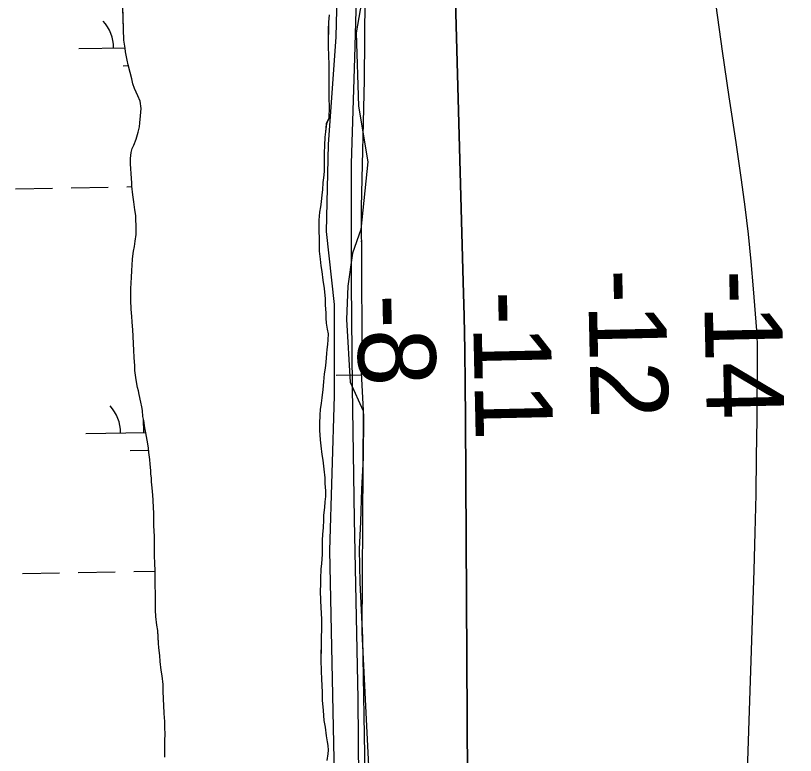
# Model space of a CAD drawing. Extents: x 3925854 to 3964121, y 224593 to 250589.
# Drawn here: x 3942477 to 3943151, y 240491 to 241130 of the extents above; entities that cross this region are included whole.
import ezdxf

# ---------------------------------------------------------------- set-up
doc = ezdxf.new("R2010")
doc.units = 0
for name, color, linetype in [('V-RIVR-EDGE', 7, 'Continuous'), ('V-RIVR-JETY', 7, 'Continuous'), ('V-RIVR-RANG', 7, 'Continuous'), ('V-TOPO-DPTH', 7, 'Continuous'), ('V-TOPO-MINR', 7, 'Continuous'), ('V-TOPO-SHOR', 7, 'Continuous'), ('V-WETL-SWMP', 7, 'Continuous')]:
    doc.layers.add(name, color=color, linetype=linetype)

msp = doc.modelspace()

# ---------------------------------------------------------------- linework, layer by layer
at = {"layer": 'V-RIVR-EDGE'}
msp.add_lwpolyline([(3942781.233, 241173.826), (3942770.996, 241115.474), (3942773.043, 241052.004), (3942781.233, 241003.889), (3942775.091, 240945.538), (3942767.925, 240925.063), (3942763.83, 240896.399), (3942762.806, 240867.736), (3942765.877, 240813.479), (3942777.138, 240788.91), (3942776.115, 240597.475), (3942781.233, 240493.057), (3942784.304, 240431.634), (3942779.186, 240308.789), (3942774.067, 240215.631), (3942769.972, 240146.018), (3942766.901, 240096.88), (3942778.162, 240084.595), (3942767.925, 240046.718), (3942764.854, 240017.03), (3942759.735, 239975.058), (3942740.285, 239935.133), (3942733.119, 239893.161), (3942732.095, 239848.118)], dxfattribs=at)
at = {"layer": 'V-RIVR-JETY'}
for points in [[(3942501.881, 238496.007), (3942530.957, 238578.48), (3942555.82, 238617.728), (3942596.956, 238684.087), (3942673.397, 238798.99), (3942694.77, 238864.612), (3942700.089, 238923.816), (3942705.303, 239063.915), (3942714.359, 239211.498), (3942718.996, 239386.408), (3942726.512, 239566.929), (3942728.732, 239690.128), (3942735.923, 239929.912), (3942744.955, 240165.915), (3942749.64, 240345.527), (3942752.055, 240487.535), (3942748.285, 240668.175), (3942752.491, 240801.701), (3942752.37, 240880.714), (3942745.499, 240943.807), (3942747.22, 241019.038), (3942753.828, 241112.093), (3942757.154, 241251.271)], [(3942538.571, 238553.806), (3942560.622, 238594.024), (3942630.365, 238697.71), (3942697.234, 238796.723), (3942709.735, 238822.929), (3942715.631, 238847.327), (3942722.113, 238928.151), (3942724.245, 239042.886), (3942729.685, 239204.617), (3942737.78, 239350.33), (3942741.958, 239481.033), (3942746.566, 239653.121), (3942749.476, 239843.095), (3942757.257, 240049.011), (3942767.313, 240202.23), (3942774.055, 240398.75), (3942772.697, 240539.858), (3942769.602, 240695.094), (3942767.962, 240808.926), (3942767.018, 240899.237), (3942767.151, 241002.704), (3942769.979, 241093.915), (3942774.399, 241248.132)]]:
    msp.add_lwpolyline(points, dxfattribs=at)
at = {"layer": 'V-TOPO-DPTH'}
msp.add_lwpolyline([(3942983.62, 238887.801), (3942658.91, 239021.11), (3942869.48, 240055.28), (3942865.529, 240782.275), (3942865.271, 240811.75), (3942864.883, 240841.222), (3942864.3, 240870.691), (3942863.587, 240900.157), (3942843.55, 241628.53), (3943150.608, 241695.11)], dxfattribs=at)
at = {"layer": 'V-TOPO-MINR'}
for points in [[(3942843.55, 241628.53), (3942863.587, 240900.157), (3942864.3, 240870.691), (3942864.883, 240841.222), (3942865.271, 240811.75), (3942865.529, 240782.275), (3942869.48, 240055.28), (3942658.91, 239021.11)], [(3943081.741, 241139.181), (3943087.446, 241099.636), (3943093.21, 241060.099), (3943099.014, 241020.569), (3943103.746, 240988.499), (3943106.958, 240964.979), (3943109.832, 240941.421), (3943112.199, 240917.807), (3943114.227, 240894.156), (3943116.91, 240858.352), (3943117.27, 240852.572), (3943117.535, 240846.788), (3943117.655, 240841), (3943117.679, 240835.208), (3943117.233, 240781.568), (3943116.842, 240748.956), (3943116.292, 240716.348), (3943115.504, 240683.745), (3943114.557, 240651.144), (3943096.096, 240086.809)]]:
    msp.add_lwpolyline(points, dxfattribs=at)
at = {"layer": 'V-TOPO-SHOR'}
for points in [[(3942583.969, 241034.288), (3942584.342, 241037.821), (3942584.742, 241043.877), (3942585.313, 241050.1), (3942584.369, 241056.509), (3942582.392, 241060.908), (3942579.599, 241067.504), (3942578.294, 241071.557), (3942577.16, 241075.78), (3942575.87, 241081.181), (3942574.086, 241087.935), (3942573.287, 241091.984), (3942571.845, 241099.07), (3942571.538, 241102.105), (3942570.903, 241105.648), (3942570.434, 241109.187), (3942569.156, 241148.433)], [(3942747.664, 241131.193), (3942747.093, 241124.799), (3942747.025, 241118.401), (3942746.962, 241112.173), (3942746.863, 241102.744), (3942747.136, 241096.512), (3942747.543, 241087.247), (3942747.609, 241077.142), (3942747.535, 241070.24), (3942747.588, 241059.126), (3942747.846, 241051.546), (3942747.408, 241041.786), (3942745.337, 241036.924), (3942744.76, 241029.858), (3942744.039, 241025.32), (3942743.629, 241018.252), (3942743.394, 241011.686), (3942743.519, 241007.645), (3942743.488, 241004.614), (3942743.601, 240999.224), (3942743.396, 240995.691), (3942742.833, 240990.139), (3942742.454, 240986.102), (3942741.883, 240979.711), (3942741.334, 240975.506), (3942740.766, 240969.45), (3942740.215, 240965.08), (3942739.325, 240960.373), (3942738.917, 240953.644), (3942738.862, 240948.255), (3942738.974, 240942.865), (3942739.103, 240939.16), (3942739.193, 240931.583), (3942739.144, 240926.868), (3942739.914, 240919.788), (3942740.699, 240914.224), (3942741.321, 240909.333), (3942742.419, 240901.577), (3942743.525, 240894.493), (3942744.275, 240885.73), (3942744.389, 240880.51), (3942744.817, 240873.096), (3942744.942, 240868.885), (3942745.235, 240864.672), (3942746.189, 240859.276), (3942746.988, 240855.225), (3942746.599, 240850.179), (3942746.222, 240846.14), (3942745.841, 240841.936), (3942745.467, 240838.235), (3942744.885, 240830.831), (3942744.326, 240825.617), (3942743.601, 240820.743), (3942743.023, 240813.845), (3942742.452, 240807.283), (3942741.366, 240800.054), (3942740.811, 240795.346), (3942739.912, 240789.8), (3942739.697, 240785.255), (3942739.447, 240777.512), (3942739.56, 240772.123), (3942740.148, 240763.698), (3942740.596, 240758.473), (3942741.53, 240751.056), (3942742.321, 240745.995), (3942743.083, 240738.409), (3942744.014, 240730.823), (3942744.133, 240725.939), (3942744.574, 240719.705), (3942744.522, 240714.822), (3942744.137, 240710.112), (3942743.75, 240705.234), (3942743.009, 240698.674), (3942742.964, 240694.295), (3942742.56, 240688.069), (3942742.161, 240682.013), (3942741.774, 240677.133), (3942741.864, 240669.555), (3942741.645, 240664.675), (3942741.059, 240656.936), (3942740.502, 240651.889)], [(3942605.83, 240495.752), (3942605.918, 240504.337), (3942606.133, 240508.714), (3942605.867, 240515.62), (3942605.746, 240520.166), (3942605.312, 240527.074), (3942604.884, 240534.488), (3942604.597, 240539.374), (3942604.341, 240547.122), (3942604.224, 240552.174), (3942603.46, 240559.59), (3942602.672, 240564.651), (3942601.906, 240572.069), (3942601.455, 240577.293), (3942600.681, 240583.867), (3942600.388, 240588.08), (3942600.097, 240592.461), (3942599.659, 240599.033), (3942599.032, 240603.415), (3942598.101, 240611.003), (3942597.818, 240616.393), (3942597.738, 240624.815), (3942597.625, 240630.203), (3942597.544, 240638.454), (3942597.453, 240646.032), (3942597.501, 240650.579), (3942597.232, 240657.149), (3942596.794, 240663.551), (3942596.855, 240669.613), (3942596.745, 240675.169), (3942596.802, 240680.725), (3942596.673, 240684.43), (3942596.395, 240689.99), (3942596.268, 240694.033), (3942596.167, 240700.601), (3942595.876, 240704.982), (3942595.606, 240711.552), (3942595.315, 240715.932), (3942594.875, 240722.166), (3942594.424, 240727.391), (3942594.291, 240730.76), (3942593.818, 240733.965), (3942593.685, 240737.334), (3942593.235, 240742.558), (3942592.772, 240746.603), (3942591.993, 240752.673), (3942591.701, 240756.886), (3942590.589, 240763.464), (3942589.309, 240769.877), (3942588.512, 240774.094), (3942587.566, 240780.334), (3942586.929, 240783.877), (3942586.476, 240788.931), (3942586.005, 240792.304), (3942585.206, 240796.353), (3942583.588, 240802.77), (3942582.947, 240805.975), (3942582.306, 240809.014), (3942581.348, 240813.907), (3942580.711, 240817.618), (3942579.933, 240823.686), (3942579.808, 240827.897), (3942579.374, 240834.637), (3942579.107, 240841.542), (3942578.821, 240846.429), (3942578.391, 240853.675), (3942578.106, 240858.559), (3942577.676, 240865.805), (3942577.383, 240870.186), (3942576.609, 240876.592), (3942576.353, 240884.339), (3942576.41, 240889.896), (3942576.451, 240893.936), (3942576.849, 240899.658), (3942576.892, 240903.867), (3942577.295, 240910.261), (3942577.506, 240914.3), (3942577.901, 240920.022), (3942578.815, 240926.915), (3942579.527, 240930.78), (3942580.25, 240935.486), (3942580.983, 240941.204), (3942581.061, 240948.782), (3942580.781, 240954.172), (3942580.648, 240957.541), (3942580.025, 240962.43), (3942579.087, 240969.512), (3942578.141, 240975.584), (3942577.377, 240983), (3942577.24, 240986.033), (3942576.937, 240989.404), (3942576.652, 240994.288), (3942576.349, 240997.659), (3942576.23, 241002.544), (3942576.107, 241006.922), (3942576.834, 241011.967), (3942577.713, 241015.493), (3942579.091, 241018.51), (3942580.998, 241023.71), (3942582.743, 241029.586), (3942583.969, 241034.288)], [(3942740.502, 240651.889), (3942740.25, 240643.81), (3942740.365, 240638.59), (3942740.14, 240633.203), (3942740.224, 240624.952), (3942740.664, 240618.718), (3942741.233, 240608.777), (3942741.162, 240601.873), (3942740.883, 240591.269), (3942740.809, 240584.199), (3942740.701, 240573.59), (3942740.934, 240563.653), (3942741.201, 240556.915), (3942741.758, 240545.629), (3942741.852, 240538.555), (3942742.603, 240529.794), (3942743.187, 240521.198), (3942744.307, 240515.464), (3942745.237, 240507.876), (3942746.196, 240502.815), (3942746.667, 240499.442), (3942746.962, 240495.398), (3942746.593, 240492.371), (3942745.69, 240486.487)], [(3942605.764, 240489.522), (3942605.83, 240495.752)]]:
    msp.add_lwpolyline(points, dxfattribs=at)
at = {"layer": 'V-WETL-SWMP'}
for p, q in [((3942778.222, 241074.964), (3942779.36, 241184.692)), ((3942570.434, 241109.188), (3942569.157, 241148.434)), ((3942747.663, 241131.193), (3942747.092, 241124.8)), ((3942747.092, 241124.8), (3942746.863, 241102.745)), ((3942570.903, 241105.648), (3942570.434, 241109.188)), ((3942531.516, 241101.842), (3942571.456, 241102.568)), ((3942571.539, 241102.105), (3942570.903, 241105.648)), ((3942571.845, 241099.071), (3942571.539, 241102.105)), ((3942573.287, 241091.984), (3942571.845, 241099.071)), ((3942746.863, 241102.745), (3942747.135, 241096.512)), ((3942747.135, 241096.512), (3942747.544, 241087.247)), ((3942569.791, 241087.104), (3942574.284, 241087.186)), ((3942574.086, 241087.935), (3942573.287, 241091.984)), ((3942575.869, 241081.181), (3942574.086, 241087.935)), ((3942747.544, 241087.247), (3942747.608, 241077.143)), ((3942577.16, 241075.78), (3942575.869, 241081.181)), ((3942578.294, 241071.558), (3942577.16, 241075.78)), ((3942747.608, 241077.143), (3942747.536, 241070.24)), ((3942775.667, 240964.847), (3942778.222, 241074.964)), ((3942579.599, 241067.504), (3942578.294, 241071.558)), ((3942582.393, 241060.908), (3942579.599, 241067.504)), ((3942747.536, 241070.24), (3942747.589, 241059.127)), ((3942584.368, 241056.509), (3942582.393, 241060.908)), ((3942747.589, 241059.127), (3942747.847, 241051.547)), ((3942585.312, 241050.101), (3942584.368, 241056.509)), ((3942584.742, 241043.877), (3942585.312, 241050.101)), ((3942747.847, 241051.547), (3942747.409, 241041.786)), ((3942584.343, 241037.82), (3942584.742, 241043.877)), ((3942747.409, 241041.786), (3942745.338, 241036.924)), ((3942582.742, 241029.586), (3942583.969, 241034.287)), ((3942583.969, 241034.287), (3942584.343, 241037.82)), ((3942745.338, 241036.924), (3942744.76, 241029.858)), ((3942580.997, 241023.71), (3942582.742, 241029.586)), ((3942744.039, 241025.319), (3942743.629, 241018.252)), ((3942744.76, 241029.858), (3942744.039, 241025.319)), ((3942577.713, 241015.494), (3942579.091, 241018.51)), ((3942579.091, 241018.51), (3942580.997, 241023.71)), ((3942743.629, 241018.252), (3942743.393, 241011.687)), ((3942576.108, 241006.923), (3942576.834, 241011.967)), ((3942576.834, 241011.967), (3942577.713, 241015.494)), ((3942743.393, 241011.687), (3942743.519, 241007.645)), ((3942576.231, 241002.544), (3942576.108, 241006.923)), ((3942743.519, 241007.645), (3942743.488, 241004.614)), ((3942576.349, 240997.66), (3942576.231, 241002.544)), ((3942743.6, 240999.225), (3942743.395, 240995.691)), ((3942743.488, 241004.614), (3942743.6, 240999.225)), ((3942576.651, 240994.289), (3942576.349, 240997.66)), ((3942576.937, 240989.403), (3942576.651, 240994.289)), ((3942743.395, 240995.691), (3942742.832, 240990.14)), ((3942577.239, 240986.032), (3942576.937, 240989.403)), ((3942577.376, 240983), (3942577.239, 240986.032)), ((3942742.454, 240986.103), (3942741.882, 240979.711)), ((3942742.832, 240990.14), (3942742.454, 240986.103)), ((3942476.865, 240980.757), (3942508.859, 240981.339)), ((3942524.857, 240981.63), (3942556.851, 240982.212)), ((3942572.849, 240982.503), (3942577.419, 240982.586)), ((3942578.141, 240975.583), (3942577.376, 240983)), ((3942741.882, 240979.711), (3942741.333, 240975.507)), ((3942579.088, 240969.512), (3942578.141, 240975.583)), ((3942741.333, 240975.507), (3942740.766, 240969.451)), ((3942580.025, 240962.43), (3942579.088, 240969.512)), ((3942740.215, 240965.079), (3942739.324, 240960.374)), ((3942740.766, 240969.451), (3942740.215, 240965.079)), ((3942776.323, 240853.082), (3942775.667, 240964.847)), ((3942580.648, 240957.541), (3942580.025, 240962.43)), ((3942580.781, 240954.172), (3942580.648, 240957.541)), ((3942739.324, 240960.374), (3942738.918, 240953.643)), ((3942581.062, 240948.781), (3942580.781, 240954.172)), ((3942738.918, 240953.643), (3942738.862, 240948.255)), ((3942580.983, 240941.204), (3942581.062, 240948.781)), ((3942738.862, 240948.255), (3942738.974, 240942.866)), ((3942580.25, 240935.487), (3942580.983, 240941.204)), ((3942738.974, 240942.866), (3942739.104, 240939.16)), ((3942739.104, 240939.16), (3942739.194, 240931.582)), ((3942578.814, 240926.915), (3942579.528, 240930.78)), ((3942579.528, 240930.78), (3942580.25, 240935.487)), ((3942739.194, 240931.582), (3942739.145, 240926.868)), ((3942775.054, 240935.429), (3942775.84, 240935.443)), ((3942577.901, 240920.021), (3942578.814, 240926.915)), ((3942739.145, 240926.868), (3942739.914, 240919.788)), ((3942577.505, 240914.3), (3942577.901, 240920.021)), ((3942739.914, 240919.788), (3942740.698, 240914.223)), ((3942577.295, 240910.261), (3942577.505, 240914.3)), ((3942740.698, 240914.223), (3942741.321, 240909.334)), ((3942576.848, 240899.658), (3942576.892, 240903.867)), ((3942576.892, 240903.867), (3942577.295, 240910.261)), ((3942741.321, 240909.334), (3942742.419, 240901.577)), ((3942576.452, 240893.937), (3942576.848, 240899.658)), ((3942742.419, 240901.577), (3942743.524, 240894.494)), ((3942576.352, 240884.34), (3942576.452, 240893.937)), ((3942743.524, 240894.494), (3942744.275, 240885.73)), ((3942576.609, 240876.592), (3942576.352, 240884.34)), ((3942744.275, 240885.73), (3942744.389, 240880.509)), ((3942744.389, 240880.509), (3942744.817, 240873.096)), ((3942577.384, 240870.186), (3942576.609, 240876.592)), ((3942577.675, 240865.805), (3942577.384, 240870.186)), ((3942744.817, 240873.096), (3942744.942, 240868.885)), ((3942578.105, 240858.56), (3942577.675, 240865.805)), ((3942744.942, 240868.885), (3942745.235, 240864.673)), ((3942745.235, 240864.673), (3942746.189, 240859.275)), ((3942578.391, 240853.674), (3942578.105, 240858.56)), ((3942746.189, 240859.275), (3942746.989, 240855.225)), ((3942578.821, 240846.429), (3942578.391, 240853.674)), ((3942746.6, 240850.178), (3942746.222, 240846.141)), ((3942746.989, 240855.225), (3942746.6, 240850.178)), ((3942775.797, 240821.82), (3942776.323, 240853.082)), ((3942579.108, 240841.543), (3942578.821, 240846.429)), ((3942746.222, 240846.141), (3942745.841, 240841.935)), ((3942579.373, 240834.637), (3942579.108, 240841.543)), ((3942745.466, 240838.235), (3942744.884, 240830.832)), ((3942745.841, 240841.935), (3942745.466, 240838.235)), ((3942579.808, 240827.897), (3942579.373, 240834.637)), ((3942744.884, 240830.832), (3942744.325, 240825.618)), ((3942579.933, 240823.686), (3942579.808, 240827.897)), ((3942580.711, 240817.617), (3942579.933, 240823.686)), ((3942744.325, 240825.618), (3942743.601, 240820.743)), ((3942581.347, 240813.906), (3942580.711, 240817.617)), ((3942743.601, 240820.743), (3942743.024, 240813.845)), ((3942753.748, 240819.59), (3942775.884, 240819.993)), ((3942777.619, 240783.473), (3942775.797, 240821.82)), ((3942582.306, 240809.013), (3942581.347, 240813.906)), ((3942743.024, 240813.845), (3942742.451, 240807.284)), ((3942582.948, 240805.975), (3942582.306, 240809.013)), ((3942583.588, 240802.769), (3942582.948, 240805.975)), ((3942585.206, 240796.354), (3942583.588, 240802.769)), ((3942742.451, 240807.284), (3942741.366, 240800.055)), ((3942586.005, 240792.305), (3942585.206, 240796.354)), ((3942741.366, 240800.055), (3942740.812, 240795.346)), ((3942586.476, 240788.932), (3942586.005, 240792.305)), ((3942739.912, 240789.799), (3942739.697, 240785.255)), ((3942740.812, 240795.346), (3942739.912, 240789.799)), ((3942586.928, 240783.876), (3942586.476, 240788.932)), ((3942587.565, 240780.334), (3942586.928, 240783.876)), ((3942739.697, 240785.255), (3942739.448, 240777.512)), ((3942777.454, 240748.172), (3942777.619, 240783.473)), ((3942587.556, 240770.131), (3942587.349, 240781.536)), ((3942588.511, 240774.094), (3942587.565, 240780.334)), ((3942739.448, 240777.512), (3942739.56, 240772.123)), ((3942537.564, 240769.222), (3942589.255, 240770.162)), ((3942589.309, 240769.876), (3942588.511, 240774.094)), ((3942590.589, 240763.464), (3942589.309, 240769.876)), ((3942739.56, 240772.123), (3942740.147, 240763.698)), ((3942591.7, 240756.886), (3942590.589, 240763.464)), ((3942740.147, 240763.698), (3942740.597, 240758.473)), ((3942591.993, 240752.673), (3942591.7, 240756.886)), ((3942740.597, 240758.473), (3942741.531, 240751.055)), ((3942575.839, 240754.484), (3942591.847, 240754.775)), ((3942592.772, 240746.604), (3942591.993, 240752.673)), ((3942741.531, 240751.055), (3942742.32, 240745.995)), ((3942593.235, 240742.558), (3942592.772, 240746.604)), ((3942593.686, 240737.333), (3942593.235, 240742.558)), ((3942742.32, 240745.995), (3942743.083, 240738.41)), ((3942775.963, 240721.156), (3942777.454, 240748.172)), ((3942593.819, 240733.964), (3942593.686, 240737.333)), ((3942743.083, 240738.41), (3942744.015, 240730.823)), ((3942594.291, 240730.76), (3942593.819, 240733.964)), ((3942594.425, 240727.391), (3942594.291, 240730.76)), ((3942744.015, 240730.823), (3942744.133, 240725.939)), ((3942594.876, 240722.167), (3942594.425, 240727.391)), ((3942595.316, 240715.932), (3942594.876, 240722.167)), ((3942744.133, 240725.939), (3942744.573, 240719.705)), ((3942595.607, 240711.551), (3942595.316, 240715.932)), ((3942744.573, 240719.705), (3942744.523, 240714.822)), ((3942775.265, 240692.719), (3942775.963, 240721.156)), ((3942595.876, 240704.982), (3942595.607, 240711.551)), ((3942744.137, 240710.112), (3942743.75, 240705.233)), ((3942744.523, 240714.822), (3942744.137, 240710.112)), ((3942596.167, 240700.601), (3942595.876, 240704.982)), ((3942743.75, 240705.233), (3942743.008, 240698.673)), ((3942596.267, 240694.033), (3942596.167, 240700.601)), ((3942743.008, 240698.673), (3942742.963, 240694.296)), ((3942596.394, 240689.991), (3942596.267, 240694.033)), ((3942596.673, 240684.431), (3942596.394, 240689.991)), ((3942742.561, 240688.07), (3942742.162, 240682.013)), ((3942742.963, 240694.296), (3942742.561, 240688.07)), ((3942774.014, 240669.332), (3942775.265, 240692.719)), ((3942596.803, 240680.725), (3942596.673, 240684.431)), ((3942742.162, 240682.013), (3942741.774, 240677.134)), ((3942596.745, 240675.169), (3942596.803, 240680.725)), ((3942596.856, 240669.612), (3942596.745, 240675.169)), ((3942741.774, 240677.134), (3942741.864, 240669.556)), ((3942596.793, 240663.551), (3942596.856, 240669.612)), ((3942741.864, 240669.556), (3942741.645, 240664.675)), ((3942774.521, 240640.479), (3942774.014, 240669.332)), ((3942597.232, 240657.148), (3942596.793, 240663.551)), ((3942741.645, 240664.675), (3942741.06, 240656.935)), ((3942597.5, 240650.578), (3942597.232, 240657.148)), ((3942741.06, 240656.935), (3942740.502, 240651.89)), ((3942482.913, 240648.137), (3942514.907, 240648.719)), ((3942530.905, 240649.01), (3942562.899, 240649.592)), ((3942578.897, 240649.883), (3942597.496, 240650.221)), ((3942597.453, 240646.032), (3942597.5, 240650.578)), ((3942740.502, 240651.89), (3942740.25, 240643.81)), ((3942597.543, 240638.454), (3942597.453, 240646.032)), ((3942740.25, 240643.81), (3942740.364, 240638.589)), ((3942597.626, 240630.203), (3942597.543, 240638.454)), ((3942740.364, 240638.589), (3942740.14, 240633.203)), ((3942776.847, 240592.444), (3942774.521, 240640.479)), ((3942597.738, 240624.814), (3942597.626, 240630.203)), ((3942740.14, 240633.203), (3942740.223, 240624.952)), ((3942597.819, 240616.394), (3942597.738, 240624.814)), ((3942740.223, 240624.952), (3942740.663, 240618.717)), ((3942598.1, 240611.003), (3942597.819, 240616.394)), ((3942740.663, 240618.717), (3942741.234, 240608.777)), ((3942599.032, 240603.416), (3942598.1, 240611.003)), ((3942741.234, 240608.777), (3942741.162, 240601.874)), ((3942599.66, 240599.032), (3942599.032, 240603.416)), ((3942741.162, 240601.874), (3942740.884, 240591.269)), ((3942600.388, 240588.079), (3942599.66, 240599.032)), ((3942600.681, 240583.867), (3942600.388, 240588.079)), ((3942740.884, 240591.269), (3942740.7, 240573.591)), ((3942780.056, 240396.129), (3942776.847, 240592.444)), ((3942601.455, 240577.292), (3942600.681, 240583.867)), ((3942601.906, 240572.068), (3942601.455, 240577.292)), ((3942740.7, 240573.591), (3942740.934, 240563.654)), ((3942602.671, 240564.651), (3942601.906, 240572.068)), ((3942603.46, 240559.591), (3942602.671, 240564.651)), ((3942740.934, 240563.654), (3942741.201, 240556.916)), ((3942604.225, 240552.175), (3942603.46, 240559.591)), ((3942741.201, 240556.916), (3942741.757, 240545.629)), ((3942604.341, 240547.122), (3942604.225, 240552.175)), ((3942604.597, 240539.374), (3942604.341, 240547.122)), ((3942741.757, 240545.629), (3942741.852, 240538.556)), ((3942604.884, 240534.488), (3942604.597, 240539.374)), ((3942605.312, 240527.075), (3942604.884, 240534.488)), ((3942741.852, 240538.556), (3942742.603, 240529.793)), ((3942605.745, 240520.167), (3942605.312, 240527.075)), ((3942742.603, 240529.793), (3942743.187, 240521.199)), ((3942605.866, 240515.619), (3942605.745, 240520.167)), ((3942743.187, 240521.199), (3942744.307, 240515.463)), ((3942606.132, 240508.713), (3942605.866, 240515.619)), ((3942744.307, 240515.463), (3942745.238, 240507.876)), ((3942605.918, 240504.337), (3942606.132, 240508.713)), ((3942745.238, 240507.876), (3942746.196, 240502.815)), ((3942605.764, 240489.521), (3942605.918, 240504.337)), ((3942746.196, 240502.815), (3942746.666, 240499.442)), ((3942746.666, 240499.442), (3942746.961, 240495.398)), ((3942746.961, 240495.398), (3942746.593, 240492.371)), ((3942746.593, 240492.371), (3942745.69, 240486.487))]:
    msp.add_line(p, q, dxfattribs=at)
for centre in [(3942526.266, 241102.221), (3942532.314, 240769.601)]:
    msp.add_arc(centre, 35.246, 0.269879, 41.813537, dxfattribs=at)

# ---------------------------------------------------------------- texts
at = {"layer": 'V-RIVR-RANG'}
for s, p in [('-12', (3942971.241, 240910.846)), ('-14', (3943071.281, 240910.149)), ('-8', (3942771.674, 240889.032)), ('-11', (3942871.632, 240892.028))]:
    msp.add_text(s, height=67, rotation=271.263028, dxfattribs=at).set_placement(p)

doc.saveas('drawing.dxf')
